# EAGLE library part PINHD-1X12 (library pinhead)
PIN HEADER
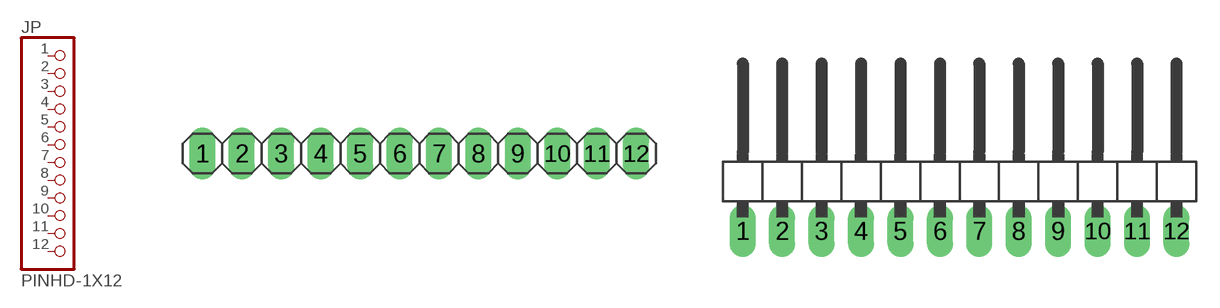
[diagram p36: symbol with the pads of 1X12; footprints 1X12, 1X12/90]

Designator prefix JP

## PINHD-1X12  [1X12]
1  1  pas
2  2  pas
3  3  pas
4  4  pas
5  5  pas
6  6  pas
7  7  pas
8  8  pas
9  9  pas
10  10  pas
11  11  pas
12  12  pas

## PINHD-1X12/90  [1X12/90]
Pads as for 1X12

## Footprint 1X12 (pad centres in mm)
PIN HEADER
drill 1.016 pad 1.67 long: 1 -13.97,0; 2 -11.43,0; 3 -8.89,0; 4 -6.35,0; 5 -3.81,0; 6 -1.27,0; 7 1.27,0; 8 3.81,0; 9 6.35,0; 10 8.89,0; 11 11.43,0; 12 13.97,0

## Footprint 1X12/90 (pad centres in mm)
PIN HEADER
drill 1.016 pad 1.67 long: 1 -13.97,-3.81; 2 -11.43,-3.81; 3 -8.89,-3.81; 4 -6.35,-3.81; 5 -3.81,-3.81; 6 -1.27,-3.81; 7 1.27,-3.81; 8 3.81,-3.81; 9 6.35,-3.81; 10 8.89,-3.81; 11 11.43,-3.81; 12 13.97,-3.81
